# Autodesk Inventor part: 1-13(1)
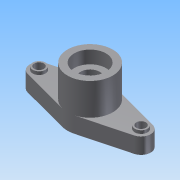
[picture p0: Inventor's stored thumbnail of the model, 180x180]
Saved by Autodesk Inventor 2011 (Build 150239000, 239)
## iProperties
Created: 2014-02
Part Number: 1-13(1)
Document SubType Name: Modeling
Designer: Administrator
Density: 1 g/cm^3
Author: Administrator
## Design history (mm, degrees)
sketch "草图1"
  geometry: L1 (-16.746, 2.899)-(-1.827, 6.868); L2 (-16.746, -2.899)-(-1.827, -6.868); L3 (16.793, 2.9)-(1.821, 6.869); L4 (16.793, -2.9)-(1.821, -6.869); L5 (-0.003, 8.835)-(-0.003, -12.892); A1 r 3 centre (16.024, 0) between (16.793, -2.9) and (16.793, 2.9); A2 r 3 centre (-15.974, 0) between (-16.746, 2.899) and (-16.746, -2.899); A3 r 7.106 centre (0, 0) between (-1.827, -6.868) and (1.821, -6.869); A4 r 7.106 centre (0, 0) between (1.821, 6.869) and (-1.827, 6.868); 1 further point
  constraints: 10 end point, 8 point on circle, 8 tangent, 4 centre point, 2 horizontal alignment, 1 coincident, 1 vertical
  dimensions: "d3" = 6 diameter of A1; "d4" = 6 diameter of A2; "d21" = 31.99831 distance of A1.centre A2.centre
extrude "拉伸1" new body sketch "草图1" distance "d5" = 5; taper "d6" = 0 deg
sketch "草图2"
  geometry: C1 r 7.106 at (0, 0); A1 r 7.106 centre (0, 0) between (-1.827, -6.868) and (1.821, -6.869) reference; A2 r 7.106 centre (0, 0) between (1.821, 6.869) and (-1.827, 6.868) reference
  constraints: 1 centre point, 1 coincident, 1 concentric
extrude "拉伸2" join sketch "草图2" distance "d7" = 10; taper "d8" = 0 deg
sketch "草图3"
  geometry: C1 r 7.106 at (0, 0) reference; C2 r 5 at (0, 0)
  constraints: 1 centre point, 1 coincident
  dimensions: "d9" = 10 diameter of C2
extrude "拉伸3" cut sketch "草图3" distance "d10" = 4; taper "d11" = 0 deg
sketch "草图4"
  geometry: C1 r 5 at (0, 0) reference; C2 r 3 at (0, 0)
  constraints: 1 centre point, 1 coincident
  dimensions: "d12" = 6 diameter of C2
extrude "拉伸4" cut sketch "草图4" stored distance "d13" = 4; taper "d14" = 0 deg
sketch "草图5"
  geometry: C1 r 2 at (16.024, 0); A1 r 3 centre (16.024, 0) between (16.793, -2.9) and (16.793, 2.9) reference
  constraints: 1 centre point, 1 coincident
  dimensions: "d15" = 4 diameter of C1
extrude "拉伸5" join sketch "草图5" distance "d16" = 1; taper "d17" = 0 deg
sketch "草图6"
  geometry: C1 r 2 at (0, 0) reference; C2 r 1.5 at (0, 0); 1 further point
  constraints: 1 centre point, 1 coincident
  dimensions: "d18" = 3 diameter of C2
extrude "拉伸6" cut sketch "草图6" stored distance "d19" = 2; taper "d20" = 0 deg
mirror "镜像1"
node "实体1"
other parameters: "d0" = 14
